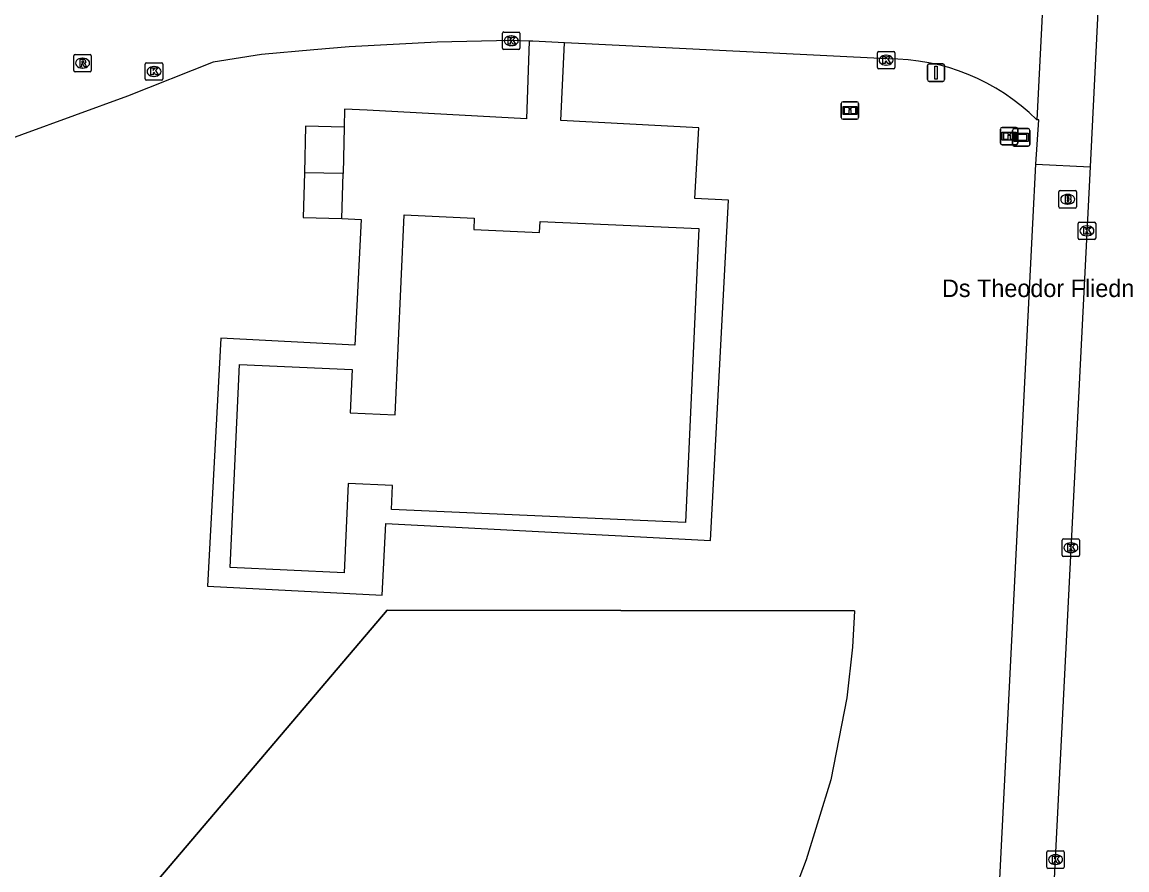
# Model space of a CAD drawing. Extents: x 161761 to 162722, y 384793 to 385405.
# Drawn here: x 162047.4 to 162110.6, y 384911.8 to 384960.2 of the extents above; entities that cross this region are included whole.
import ezdxf

# ---------------------------------------------------------------- set-up
doc = ezdxf.new("R2010")
doc.units = 0
for name, color, linetype in [('IMGEO_Brandkraan', 7, 'Continuous'), ('IMGEO_Hek', 7, 'Continuous'), ('IMGEO_Informatiebord', 7, 'Continuous'), ('IMGEO_Kolk', 7, 'Continuous'), ('IMGEO_Loofbos', 7, 'Continuous'), ('IMGEO_Openbare_ruimte_label', 7, 'Continuous'), ('IMGEO_Pand', 7, 'Continuous'), ('IMGEO_Rijbaan_lokaal_gesloten', 7, 'Continuous'), ('IMGEO_Rijbaan_lokaal_open', 7, 'Continuous'), ('IMGEO_Rioolput', 7, 'Continuous'), ('IMGEO_Verkeersbordpaal', 7, 'Continuous'), ('IMGEO_Verklikker', 7, 'Continuous'), ('IMGEO_Voetpad_open', 7, 'Continuous')]:
    doc.layers.add(name, color=color, linetype=linetype)

msp = doc.modelspace()

# ---------------------------------------------------------------- linework, layer by layer
at = {"layer": 'IMGEO_Brandkraan'}
for p, q in [((162106.694, 384949.685), (162106.694, 384950.537)), ((162106.769, 384950.611), (162107.621, 384950.611)), ((162107.695, 384950.537), (162107.695, 384949.685)), ((162107.182, 384950.391), (162107.207, 384950.391)), ((162107.621, 384949.611), (162106.769, 384949.611)), ((162107.205, 384949.831), (162107.18, 384949.831))]:
    msp.add_line(p, q, dxfattribs=at)
for points in [[(162106.694, 384949.685), (162106.694, 384950.537)], [(162106.769, 384950.611), (162107.621, 384950.611)], [(162107.695, 384950.537), (162107.695, 384949.685)], [(162107.042, 384950.311), (162107.042, 384949.911), (162107.255, 384949.911)], [(162107.273, 384950.311), (162107.042, 384950.311)], [(162107.221, 384950.23), (162107.167, 384950.23), (162107.167, 384950.154)], [(162107.167, 384950.154), (162107.22, 384950.154)], [(162107.229, 384950.078), (162107.167, 384950.078), (162107.167, 384949.997)], [(162107.167, 384949.997), (162107.229, 384949.997)], [(162107.621, 384949.611), (162106.769, 384949.611)]]:
    msp.add_lwpolyline(points, dxfattribs=at)
for centre, radius, start, end in [((162106.771, 384950.535), 0.0765, 91.55205, 178.44795), ((162106.771, 384950.535), 0.0765, 91.55205, 178.44795), ((162107.619, 384950.535), 0.0765, 1.55205, 88.44795), ((162107.619, 384950.535), 0.0765, 1.55205, 88.44795), ((162107.222, 384950.192), 0.0379, 267.82845, 90.93552), ((162107.23, 384950.037), 0.0404, 269.87594, 90.50774), ((162107.261, 384950.162), 0.251, 268.66757, 293.53466), ((162107.277, 384950.166), 0.145, 59.4692, 91.53667), ((162107.302, 384950.213), 0.0922, 285.51372, 58.15012), ((162107.307, 384950.021), 0.105, 301.31148, 78.98903), ((162106.771, 384949.687), 0.0765, 181.55205, 268.44795), ((162106.771, 384949.687), 0.0765, 181.55205, 268.44795), ((162107.619, 384949.687), 0.0765, 271.55205, 358.44795), ((162107.619, 384949.687), 0.0765, 271.55205, 358.44795)]:
    msp.add_arc(centre, radius, start, end, dxfattribs=at)
for centre, major_axis, ratio, start_param, end_param in [((162107.181, 384950.111), (-0.387, 0.002), 0.722429, 4.712389, 7.853982), ((162107.206, 384950.111), (-0.39, 0.002), 0.717154, 1.570796, 4.712389)]:
    msp.add_ellipse(centre, major_axis=major_axis, ratio=ratio, start_param=start_param, end_param=end_param, dxfattribs=at)
at = {"layer": 'IMGEO_Hek'}
msp.add_lwpolyline([(162095.006, 384926.581), (162068.261, 384926.608), (162047.547, 384902.245), (162025.753, 384894.111)], dxfattribs=at)
at = {"layer": 'IMGEO_Informatiebord'}
for p, q in [((162094.247, 384954.789), (162094.247, 384955.589)), ((162094.247, 384955.589), (162094.247, 384954.789)), ((162094.347, 384955.689), (162095.137, 384955.689)), ((162095.137, 384955.689), (162094.347, 384955.689)), ((162095.237, 384955.589), (162095.237, 384954.789)), ((162095.237, 384954.789), (162095.237, 384955.589)), ((162095.137, 384954.689), (162094.347, 384954.689)), ((162094.347, 384954.689), (162095.137, 384954.689)), ((162103.35, 384953.324), (162103.35, 384954.124)), ((162103.35, 384954.124), (162103.35, 384953.324)), ((162103.45, 384954.224), (162104.24, 384954.224)), ((162104.24, 384954.224), (162103.45, 384954.224)), ((162104.34, 384954.124), (162104.34, 384953.324)), ((162104.34, 384953.324), (162104.34, 384954.124)), ((162104.24, 384953.224), (162103.45, 384953.224)), ((162103.45, 384953.224), (162104.24, 384953.224))]:
    msp.add_line(p, q, dxfattribs=at)
for points in [[(162094.348, 384955.421), (162095.136, 384955.421), (162095.136, 384954.957), (162094.348, 384954.957), (162094.348, 384955.421)], [(162094.413, 384955.356), (162094.413, 384955.022), (162094.688, 384955.022), (162094.689, 384955.235), (162094.793, 384955.236), (162094.794, 384955.022), (162095.071, 384955.022), (162095.071, 384955.356), (162094.795, 384955.356), (162094.795, 384955.276), (162094.689, 384955.276), (162094.689, 384955.356), (162094.413, 384955.356)], [(162103.451, 384953.956), (162104.239, 384953.956), (162104.239, 384953.492), (162103.451, 384953.492), (162103.451, 384953.956)], [(162103.516, 384953.891), (162103.516, 384953.557), (162103.791, 384953.557), (162103.792, 384953.77), (162103.896, 384953.771), (162103.897, 384953.557), (162104.174, 384953.557), (162104.174, 384953.891), (162103.898, 384953.891), (162103.898, 384953.811), (162103.792, 384953.811), (162103.792, 384953.891), (162103.516, 384953.891)]]:
    msp.add_lwpolyline(points, dxfattribs=at)
for centre, start, end in [((162094.347, 384955.589), 90, 180), ((162094.347, 384955.589), 90, 180), ((162095.137, 384955.589), 0, 90), ((162095.137, 384955.589), 360, 90), ((162094.347, 384954.789), 180, 270), ((162094.347, 384954.789), 180, 270), ((162095.137, 384954.789), 270, 0), ((162095.137, 384954.789), 270, 0), ((162103.45, 384954.124), 90, 180), ((162103.45, 384954.124), 90, 180), ((162104.24, 384954.124), 0, 90), ((162104.24, 384954.124), 360, 90), ((162103.45, 384953.324), 180, 270), ((162103.45, 384953.324), 180, 270), ((162104.24, 384953.324), 270, 0), ((162104.24, 384953.324), 270, 0)]:
    msp.add_arc(centre, 0.1, start, end, dxfattribs=at)
at = {"layer": 'IMGEO_Kolk'}
for p, q in [((162074.864, 384958.749), (162074.864, 384959.601)), ((162074.939, 384959.675), (162075.791, 384959.675)), ((162075.352, 384959.455), (162075.377, 384959.455)), ((162075.865, 384959.601), (162075.865, 384958.749)), ((162075.375, 384958.895), (162075.35, 384958.895)), ((162075.791, 384958.675), (162074.939, 384958.675)), ((162096.307, 384957.64), (162096.307, 384958.492)), ((162096.382, 384958.566), (162097.234, 384958.566)), ((162096.795, 384958.346), (162096.82, 384958.346)), ((162097.308, 384958.492), (162097.308, 384957.64)), ((162054.429, 384956.992), (162054.429, 384957.844)), ((162054.504, 384957.918), (162055.356, 384957.918)), ((162054.917, 384957.698), (162054.942, 384957.698)), ((162055.43, 384957.844), (162055.43, 384956.992)), ((162097.234, 384957.566), (162096.382, 384957.566)), ((162096.818, 384957.786), (162096.793, 384957.786)), ((162055.356, 384956.918), (162054.504, 384956.918)), ((162054.94, 384957.138), (162054.915, 384957.138)), ((162107.796, 384947.88), (162107.796, 384948.732)), ((162107.871, 384948.806), (162108.723, 384948.806)), ((162108.797, 384948.732), (162108.797, 384947.88)), ((162108.307, 384948.026), (162108.282, 384948.026)), ((162108.284, 384948.586), (162108.309, 384948.586)), ((162108.723, 384947.806), (162107.871, 384947.806)), ((162106.878, 384929.759), (162106.878, 384930.611)), ((162106.953, 384930.685), (162107.805, 384930.685)), ((162107.366, 384930.465), (162107.391, 384930.465)), ((162107.879, 384930.611), (162107.879, 384929.759)), ((162107.805, 384929.685), (162106.953, 384929.685)), ((162107.389, 384929.905), (162107.364, 384929.905)), ((162106.001, 384911.927), (162106.001, 384912.779)), ((162106.076, 384912.853), (162106.928, 384912.853)), ((162106.489, 384912.633), (162106.514, 384912.633)), ((162107.002, 384912.779), (162107.002, 384911.927)), ((162106.512, 384912.073), (162106.487, 384912.073)), ((162106.928, 384911.853), (162106.076, 384911.853))]:
    msp.add_line(p, q, dxfattribs=at)
for points in [[(162074.864, 384958.749), (162074.864, 384959.601)], [(162074.939, 384959.675), (162075.791, 384959.675)], [(162075.185, 384959.375), (162075.308, 384959.375), (162075.308, 384959.224), (162075.438, 384959.375), (162075.602, 384959.375), (162075.456, 384959.224), (162075.609, 384958.975), (162075.457, 384958.975), (162075.372, 384959.139), (162075.308, 384959.072), (162075.308, 384958.975), (162075.185, 384958.975), (162075.185, 384959.375)], [(162075.865, 384959.601), (162075.865, 384958.749)], [(162075.791, 384958.675), (162074.939, 384958.675)], [(162096.307, 384957.64), (162096.307, 384958.492)], [(162096.382, 384958.566), (162097.234, 384958.566)], [(162096.628, 384958.266), (162096.751, 384958.266), (162096.751, 384958.115), (162096.881, 384958.266), (162097.045, 384958.266), (162096.899, 384958.115), (162097.052, 384957.866), (162096.9, 384957.866), (162096.815, 384958.03), (162096.751, 384957.963), (162096.751, 384957.866), (162096.628, 384957.866), (162096.628, 384958.266)], [(162097.308, 384958.492), (162097.308, 384957.64)], [(162054.429, 384956.992), (162054.429, 384957.844)], [(162054.504, 384957.918), (162055.356, 384957.918)], [(162054.75, 384957.618), (162054.873, 384957.618), (162054.873, 384957.467), (162055.003, 384957.618), (162055.167, 384957.618), (162055.021, 384957.467), (162055.174, 384957.218), (162055.022, 384957.218), (162054.937, 384957.382), (162054.873, 384957.315), (162054.873, 384957.218), (162054.75, 384957.218), (162054.75, 384957.618)], [(162055.43, 384957.844), (162055.43, 384956.992)], [(162097.234, 384957.566), (162096.382, 384957.566)], [(162055.356, 384956.918), (162054.504, 384956.918)], [(162107.796, 384947.88), (162107.796, 384948.732)], [(162107.871, 384948.806), (162108.723, 384948.806)], [(162108.797, 384948.732), (162108.797, 384947.88)], [(162108.117, 384948.506), (162108.24, 384948.506), (162108.24, 384948.355), (162108.37, 384948.506), (162108.534, 384948.506), (162108.388, 384948.355), (162108.541, 384948.106), (162108.389, 384948.106), (162108.304, 384948.27), (162108.24, 384948.203), (162108.24, 384948.106), (162108.117, 384948.106), (162108.117, 384948.506)], [(162108.723, 384947.806), (162107.871, 384947.806)], [(162106.878, 384929.759), (162106.878, 384930.611)], [(162106.953, 384930.685), (162107.805, 384930.685)], [(162107.199, 384930.385), (162107.322, 384930.385), (162107.322, 384930.234), (162107.452, 384930.385), (162107.616, 384930.385), (162107.47, 384930.234), (162107.623, 384929.985), (162107.471, 384929.985), (162107.386, 384930.149), (162107.322, 384930.082), (162107.322, 384929.985), (162107.199, 384929.985), (162107.199, 384930.385)], [(162107.879, 384930.611), (162107.879, 384929.759)], [(162107.805, 384929.685), (162106.953, 384929.685)], [(162106.001, 384911.927), (162106.001, 384912.779)], [(162106.076, 384912.853), (162106.928, 384912.853)], [(162107.002, 384912.779), (162107.002, 384911.927)], [(162106.322, 384912.553), (162106.445, 384912.553), (162106.445, 384912.402), (162106.575, 384912.553), (162106.739, 384912.553), (162106.593, 384912.402), (162106.746, 384912.153), (162106.594, 384912.153), (162106.509, 384912.317), (162106.445, 384912.25), (162106.445, 384912.153), (162106.322, 384912.153), (162106.322, 384912.553)], [(162106.928, 384911.853), (162106.076, 384911.853)]]:
    msp.add_lwpolyline(points, dxfattribs=at)
for centre, start, end in [((162074.941, 384959.599), 91.55205, 178.44795), ((162074.941, 384959.599), 91.55205, 178.44795), ((162075.789, 384959.599), 1.55205, 88.44795), ((162075.789, 384959.599), 1.55205, 88.44795), ((162074.941, 384958.751), 181.55205, 268.44795), ((162074.941, 384958.751), 181.55205, 268.44795), ((162075.789, 384958.751), 271.55205, 358.44795), ((162075.789, 384958.751), 271.55205, 358.44795), ((162096.384, 384958.49), 91.55205, 178.44795), ((162096.384, 384958.49), 91.55205, 178.44795), ((162097.232, 384958.49), 1.55205, 88.44795), ((162097.232, 384958.49), 1.55205, 88.44795), ((162054.506, 384957.842), 91.55205, 178.44795), ((162054.506, 384957.842), 91.55205, 178.44795), ((162055.354, 384957.842), 1.55205, 88.44795), ((162055.354, 384957.842), 1.55205, 88.44795), ((162096.384, 384957.642), 181.55205, 268.44795), ((162096.384, 384957.642), 181.55205, 268.44795), ((162097.232, 384957.642), 271.55205, 358.44795), ((162097.232, 384957.642), 271.55205, 358.44795), ((162054.506, 384956.994), 181.55205, 268.44795), ((162054.506, 384956.994), 181.55205, 268.44795), ((162055.354, 384956.994), 271.55205, 358.44795), ((162055.354, 384956.994), 271.55205, 358.44795), ((162107.873, 384948.73), 91.55205, 178.44795), ((162107.873, 384948.73), 91.55205, 178.44795), ((162108.721, 384948.73), 1.55205, 88.44795), ((162108.721, 384948.73), 1.55205, 88.44795), ((162107.873, 384947.882), 181.55205, 268.44795), ((162107.873, 384947.882), 181.55205, 268.44795), ((162108.721, 384947.882), 271.55205, 358.44795), ((162108.721, 384947.882), 271.55205, 358.44795), ((162106.955, 384930.609), 91.55205, 178.44795), ((162106.955, 384930.609), 91.55205, 178.44795), ((162107.803, 384930.609), 1.55205, 88.44795), ((162107.803, 384930.609), 1.55205, 88.44795), ((162106.955, 384929.761), 181.55205, 268.44795), ((162106.955, 384929.761), 181.55205, 268.44795), ((162107.803, 384929.761), 271.55205, 358.44795), ((162107.803, 384929.761), 271.55205, 358.44795), ((162106.078, 384912.777), 91.55205, 178.44795), ((162106.078, 384912.777), 91.55205, 178.44795), ((162106.926, 384912.777), 1.55205, 88.44795), ((162106.926, 384912.777), 1.55205, 88.44795), ((162106.078, 384911.929), 181.55205, 268.44795), ((162106.078, 384911.929), 181.55205, 268.44795), ((162106.926, 384911.929), 271.55205, 358.44795), ((162106.926, 384911.929), 271.55205, 358.44795)]:
    msp.add_arc(centre, 0.0765, start, end, dxfattribs=at)
for centre, major_axis, ratio, start_param, end_param in [((162075.351, 384959.175), (-0.387, 0.002), 0.722429, 4.712389, 7.853982), ((162075.376, 384959.175), (-0.39, 0.002), 0.717154, 1.570796, 4.712389), ((162096.794, 384958.066), (-0.387, 0.002), 0.722429, 4.712389, 7.853982), ((162096.819, 384958.066), (-0.39, 0.002), 0.717154, 1.570796, 4.712389), ((162054.916, 384957.418), (-0.387, 0.002), 0.722429, 4.712389, 7.853982), ((162054.941, 384957.418), (-0.39, 0.002), 0.717154, 1.570796, 4.712389), ((162108.283, 384948.306), (-0.387, 0.002), 0.722429, 4.712389, 7.853982), ((162108.308, 384948.306), (-0.39, 0.002), 0.717154, 1.570796, 4.712389), ((162107.365, 384930.185), (-0.387, 0.002), 0.722429, 4.712389, 7.853982), ((162107.39, 384930.185), (-0.39, 0.002), 0.717154, 1.570796, 4.712389), ((162106.488, 384912.353), (-0.387, 0.002), 0.722429, 4.712389, 7.853982), ((162106.513, 384912.353), (-0.39, 0.002), 0.717154, 1.570796, 4.712389)]:
    msp.add_ellipse(centre, major_axis=major_axis, ratio=ratio, start_param=start_param, end_param=end_param, dxfattribs=at)
at = {"layer": 'IMGEO_Loofbos'}
msp.add_lwpolyline([(162025.753, 384894.111), (162047.547, 384902.245), (162068.261, 384926.608), (162095.006, 384926.581), (162094.888, 384924.506), (162094.568, 384921.6), (162093.645, 384916.908), (162092.237, 384912.338), (162091.663, 384910.827), (162090.045, 384907.369), (162088.075, 384904.099), (162085.773, 384901.053), (162083.308, 384898.232), (162082.205, 384897.064), (162080.041, 384895.118), (162077.685, 384893.408), (162076.029, 384892.692), (162074.556, 384892.245), (162073.043, 384891.955), (162071.509, 384891.825)], dxfattribs=at)
at = {"layer": 'IMGEO_Pand'}
for points in [[(162063.53, 384951.631), (162063.466, 384949.074), (162065.68, 384949.018)], [(162065.744, 384951.575), (162063.53, 384951.631)], [(162065.68, 384949.018), (162065.744, 384951.575)], [(162076.981, 384948.205), (162077.01, 384948.843), (162086.087, 384948.432), (162085.325, 384931.62), (162068.51, 384932.381), (162068.571, 384933.738), (162066.045, 384933.852), (162065.814, 384928.759), (162059.291, 384929.054), (162059.817, 384940.668), (162066.269, 384940.376), (162066.157, 384937.9), (162068.723, 384937.783), (162069.241, 384949.213), (162073.248, 384949.032), (162073.219, 384948.375), (162076.981, 384948.205)]]:
    msp.add_lwpolyline(points, dxfattribs=at)
at = {"layer": 'IMGEO_Rijbaan_lokaal_gesloten'}
for points in [[(162109.542, 384973.613), (162108.474, 384951.964)], [(162108.474, 384951.964), (162105.756, 384898.085), (162105.377, 384893.854)]]:
    msp.add_lwpolyline(points, dxfattribs=at)
at = {"layer": 'IMGEO_Rijbaan_lokaal_open'}
for points in [[(162106.119, 384968.182), (162105.423, 384954.651)], [(162076.394, 384959.154), (162075.362, 384959.19), (162071.131, 384959.096), (162066.1, 384958.821), (162064.072, 384958.654), (162061.081, 384958.382), (162058.321, 384957.95), (162053.405, 384956.003), (162044.303, 384952.694), (162037.481, 384950.14), (162030.789, 384947.636), (162023.753, 384945.002), (162017.211, 384942.501), (162016.352, 384941.857), (162013.775, 384939.902), (162010.681, 384937.377), (162008.374, 384935.432), (162006.121, 384933.435), (162005.195, 384932.603), (162000, 384927.513), (161995.73, 384923.33)], [(162078.417, 384959.06), (162076.608, 384959.146), (162076.394, 384959.154)], [(162096.878, 384958.133), (162079.608, 384959.003), (162078.417, 384959.06)]]:
    msp.add_lwpolyline(points, dxfattribs=at)
msp.add_arc((162096.99, 384946.183), 11.951, 45.12063, 90.53858, dxfattribs=at)
at = {"layer": 'IMGEO_Rioolput'}
for p, q in [((162050.343, 384957.47), (162050.343, 384958.322)), ((162050.418, 384958.396), (162051.27, 384958.396)), ((162050.831, 384958.176), (162050.856, 384958.176)), ((162051.344, 384958.322), (162051.344, 384957.47)), ((162050.854, 384957.616), (162050.829, 384957.616)), ((162051.27, 384957.396), (162050.418, 384957.396))]:
    msp.add_line(p, q, dxfattribs=at)
for points in [[(162050.343, 384957.47), (162050.343, 384958.322)], [(162050.418, 384958.396), (162051.27, 384958.396)], [(162051.344, 384958.322), (162051.344, 384957.47)], [(162050.932, 384958.094), (162050.68, 384958.096), (162050.68, 384957.696)], [(162050.68, 384957.696), (162050.804, 384957.696), (162050.804, 384957.858), (162050.815, 384957.858)], [(162050.858, 384958.015), (162050.804, 384958.015), (162050.804, 384957.934)], [(162050.804, 384957.934), (162050.856, 384957.934)], [(162050.862, 384957.829), (162050.933, 384957.696), (162051.073, 384957.696), (162051.008, 384957.822)], [(162051.27, 384957.396), (162050.418, 384957.396)]]:
    msp.add_lwpolyline(points, dxfattribs=at)
for centre, radius, start, end in [((162050.42, 384958.32), 0.0765, 91.55205, 178.44795), ((162050.42, 384958.32), 0.0765, 91.55205, 178.44795), ((162051.268, 384958.32), 0.0765, 1.55205, 88.44795), ((162051.268, 384958.32), 0.0765, 1.55205, 88.44795), ((162050.814, 384957.805), 0.0533, 26.02933, 88.69889), ((162050.84, 384958.123), 0.19, 274.7715, 282.96867), ((162050.864, 384957.919), 0.0964, 77.00612, 93.18647), ((162050.878, 384957.976), 0.0378, 276.66336, 79.67722), ((162050.931, 384957.984), 0.109, 350.36119, 89.41601), ((162050.929, 384957.984), 0.112, 277.58423, 350.98172), ((162050.913, 384957.769), 0.108, 29.51342, 73.79051), ((162050.42, 384957.472), 0.0765, 181.55205, 268.44795), ((162050.42, 384957.472), 0.0765, 181.55205, 268.44795), ((162051.268, 384957.472), 0.0765, 271.55205, 358.44795), ((162051.268, 384957.472), 0.0765, 271.55205, 358.44795)]:
    msp.add_arc(centre, radius, start, end, dxfattribs=at)
for centre, major_axis, ratio, start_param, end_param in [((162050.83, 384957.896), (-0.387, 0.002), 0.722429, 4.712389, 7.853982), ((162050.855, 384957.896), (-0.39, 0.002), 0.717154, 1.570796, 4.712389)]:
    msp.add_ellipse(centre, major_axis=major_axis, ratio=ratio, start_param=start_param, end_param=end_param, dxfattribs=at)
at = {"layer": 'IMGEO_Verkeersbordpaal'}
for p, q in [((162099.167, 384956.954), (162099.167, 384957.754)), ((162099.167, 384957.754), (162099.167, 384956.954)), ((162099.267, 384957.854), (162100.057, 384957.854)), ((162100.057, 384957.854), (162099.267, 384957.854)), ((162100.157, 384957.754), (162100.157, 384956.954)), ((162100.157, 384956.954), (162100.157, 384957.754)), ((162100.057, 384956.854), (162099.267, 384956.854)), ((162099.267, 384956.854), (162100.057, 384956.854))]:
    msp.add_line(p, q, dxfattribs=at)
msp.add_lwpolyline([(162099.587, 384957.729), (162099.737, 384957.729), (162099.737, 384956.979), (162099.587, 384956.979), (162099.587, 384957.729)], dxfattribs=at)
for centre, start, end in [((162099.267, 384957.754), 90, 180), ((162099.267, 384957.754), 90, 180), ((162100.057, 384957.754), 0, 90), ((162100.057, 384957.754), 360, 90), ((162099.267, 384956.954), 180, 270), ((162099.267, 384956.954), 180, 270), ((162100.057, 384956.954), 270, 0), ((162100.057, 384956.954), 270, 0)]:
    msp.add_arc(centre, 0.1, start, end, dxfattribs=at)
at = {"layer": 'IMGEO_Verklikker'}
for p, q in [((162104.041, 384953.25), (162104.041, 384954.05)), ((162104.041, 384954.05), (162104.041, 384953.25)), ((162104.141, 384954.15), (162104.931, 384954.15)), ((162104.931, 384954.15), (162104.141, 384954.15)), ((162105.031, 384954.05), (162105.031, 384953.25)), ((162105.031, 384953.25), (162105.031, 384954.05)), ((162104.931, 384953.15), (162104.141, 384953.15)), ((162104.141, 384953.15), (162104.931, 384953.15))]:
    msp.add_line(p, q, dxfattribs=at)
for points in [[(162104.142, 384953.882), (162104.93, 384953.882), (162104.93, 384953.418), (162104.142, 384953.418), (162104.142, 384953.882)], [(162104.207, 384953.817), (162104.207, 384953.483), (162104.865, 384953.483), (162104.865, 384953.817), (162104.207, 384953.817)]]:
    msp.add_lwpolyline(points, dxfattribs=at)
for centre, start, end in [((162104.141, 384954.05), 90, 180), ((162104.141, 384954.05), 90, 180), ((162104.931, 384954.05), 0, 90), ((162104.931, 384954.05), 360, 90), ((162104.141, 384953.25), 180, 270), ((162104.141, 384953.25), 180, 270), ((162104.931, 384953.25), 270, 0), ((162104.931, 384953.25), 270, 0)]:
    msp.add_arc(centre, 0.1, start, end, dxfattribs=at)
at = {"layer": 'IMGEO_Voetpad_open'}
for points in [[(162065.68, 384949.018), (162066.787, 384948.96), (162066.409, 384941.767), (162058.744, 384942.17), (162057.997, 384927.991), (162067.98, 384927.465), (162068.197, 384931.572), (162086.764, 384930.595), (162087.789, 384950.051), (162085.874, 384950.152), (162086.087, 384954.2), (162078.205, 384954.615), (162078.417, 384959.06)], [(162076.394, 384959.154), (162076.237, 384954.719), (162067.116, 384955.199), (162065.836, 384955.267), (162065.81, 384954.232)], [(162105.37, 384952.12), (162105.544, 384954.647), (162105.423, 384954.651)], [(162065.81, 384954.232), (162063.597, 384954.287), (162063.53, 384951.631)], [(162065.81, 384954.232), (162065.744, 384951.575)], [(162102.654, 384898.009), (162105.202, 384948.727), (162105.37, 384952.12)], [(162105.37, 384952.12), (162108.474, 384951.964)]]:
    msp.add_lwpolyline(points, dxfattribs=at)

# ---------------------------------------------------------------- texts
at = {"layer": 'IMGEO_Openbare_ruimte_label'}
msp.add_text('Ds Theodor Fliednerstraat', height=1, dxfattribs=at).set_placement((162100.007, 384944.52))

doc.saveas('drawing.dxf')
